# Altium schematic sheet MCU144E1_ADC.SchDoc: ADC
size 431 x 279 mm; DrawnBy: Gustavo Martinez; DocumentNumber: 9; SheetNumber: 3; SheetTotal: 8; PageSetup: Record=PageOptions¦CenterHorizontal=True¦CenterVertical=True¦PrintScale=1.00¦XCorrection=1.00¦YCorrection=1.00¦PrintKind=0¦BorderSize=5000000¦LeftOffset=0¦BottomOffset=0¦Orientation=2¦PaperLength=1000¦PaperWidth=1000¦Scale=100¦PaperSource=15¦PrintQuality=600¦MediaType=1¦DitherType=10¦PaperKind=Letter¦PrintScaleMode=1
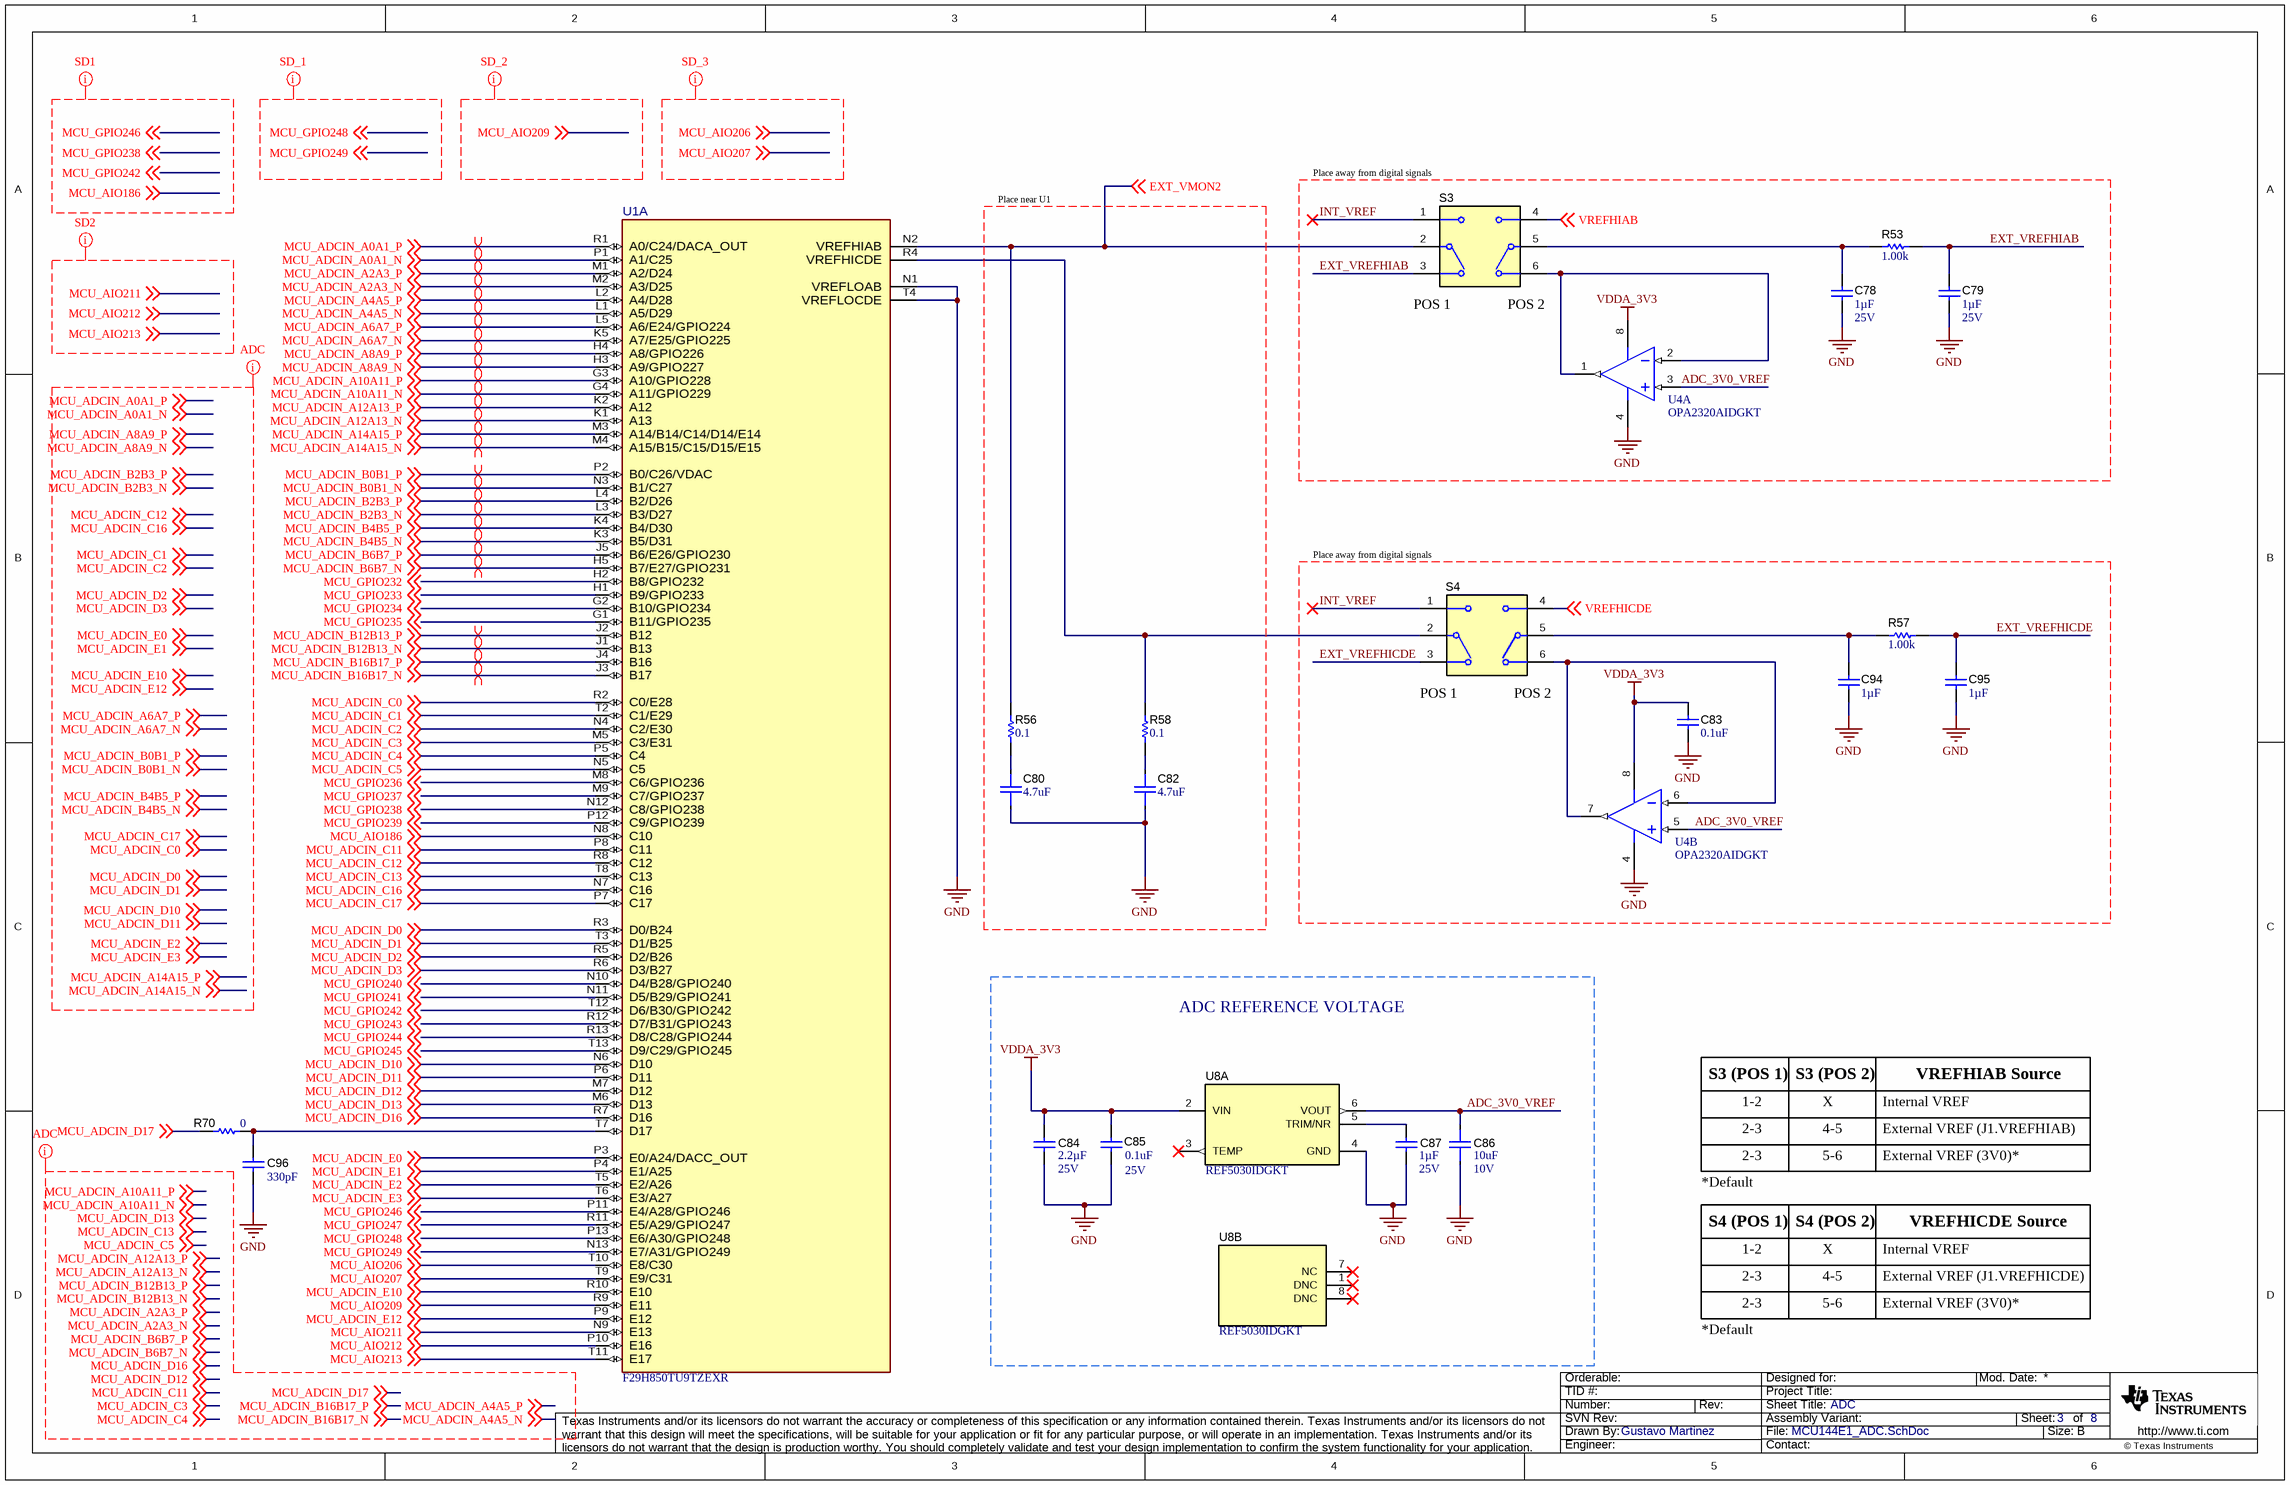
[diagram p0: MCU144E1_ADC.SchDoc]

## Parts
C78  ValueDisplayed: 1µF  VDC_V: 25V  [0402]  (hidden comment: GRM155R61E105KE11D)
C79  ValueDisplayed: 1µF  VDC_V: 25V  [0402]  (hidden comment: GRM155R61E105KE11D)
C80  ValueDisplayed: 4.7uF  [FP-GRM155C61E475ME15D_0402-MFG]  (hidden comment: GRM155C61E475ME15D)
C82  ValueDisplayed: 4.7uF  [FP-GRM155C61E475ME15D_0402-MFG]  (hidden comment: GRM155C61E475ME15D)
C83  ValueDisplayed: 0.1uF  [0402]  (hidden comment: GRM155R71E104KE14D)
C84  Value2: 25V  ValueDisplayed: 2.2µF  [0402]  (hidden comment: GRM155R61E225ME15D)
C85  VDC_V: 25V  ValueDisplayed: 0.1uF  [0402]  (hidden comment: GRM155R71E104KE14D)
C86  VDC_V: 10V  ValueDisplayed: 10uF  [FP-GRM155R61A106ME18D_0402-MFG]  (hidden comment: GRM155R61A106ME18D)
C87  ValueDisplayed: 1µF  VDC_V: 25V  [0402]  (hidden comment: GRM155R61E105KE11D)
C94  ValueDisplayed: 1µF  [0402]  (hidden comment: GRM155R61E105KE11D)
C95  ValueDisplayed: 1µF  [0402]  (hidden comment: GRM155R61E105KE11D)
C96  value 330pF  [0603]  (hidden comment: 885012006060)
R53  ValueDisplayed: 1.00k  [0402]  (hidden comment: ERJ-2RKF1001X)
R56  ValueDisplayed: 0.1  [0402]  (hidden comment: ERJ2BWFR100X)
R57  ValueDisplayed: 1.00k  [0402]  (hidden comment: ERJ-2RKF1001X)
R58  ValueDisplayed: 0.1  [0402]  (hidden comment: ERJ2BWFR100X)
R70  ValueDisplayed: 0  [0603]  (hidden comment: ERJ-3GEY0R00V)
S3  CAS-D20TA  [SW_CAS-D20TA]  (value not drawn)
S4  CAS-D20TA  [SW_CAS-D20TA]  (value not drawn)
U1  F29H850TU9TZEXR  [ZEX0256A-MFG]  (part A of 4)
U4  OPA2320AIDGKT  [DGK0008A_N]  (parts A,B of 2)
U8  REF5030IDGKT  [DGK0008A_N]  (parts A,B of 2)

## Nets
GND: C78.2 C79.2 C80.1 C82.1 C83.2 C84.2 C85.2 C86.1 C87.2 C94.2 C95.2 C96.2 U1.N1(VREFLOAB) U1.T4(VREFLOCDE) U4.4(V-) U8.4(GND)
VDDA_3V3: C83.1 C84.1 C85.1 U4.8(V+) U8.2(VIN)
ADC_3V0_VREF: C86.2 U4.3(IN_A+) U4.5(IN_B+) U8.6(VOUT)
EXT_VMON2: R56.2 S3.2(C) U1.N2(VREFHIAB) ; off-sheet EXT_VMON2
EXT_VREFHIAB: C79.1 R53.2 S3.3
EXT_VREFHICDE: C95.1 R57.2 S4.3
INT_VREF: S3.1 S4.1
MCU_ADCIN_A0A1_N: U1.P1(A1/C25) ; off-sheet MCU_ADCIN_A0A1_N
MCU_ADCIN_A0A1_P: U1.R1(A0/C24/DACA_OUT) ; off-sheet MCU_ADCIN_A0A1_P
MCU_ADCIN_A2A3_N: U1.M2(A3/D25) ; off-sheet MCU_ADCIN_A2A3_N
MCU_ADCIN_A2A3_P: U1.M1(A2/D24) ; off-sheet MCU_ADCIN_A2A3_P
MCU_ADCIN_A4A5_N: U1.L1(A5/D29) ; off-sheet MCU_ADCIN_A4A5_N
MCU_ADCIN_A4A5_P: U1.L2(A4/D28) ; off-sheet MCU_ADCIN_A4A5_P
MCU_ADCIN_A6A7_N: U1.K5(A7/E25/GPIO225) ; off-sheet MCU_ADCIN_A6A7_N
MCU_ADCIN_A6A7_P: U1.L5(A6/E24/GPIO224) ; off-sheet MCU_ADCIN_A6A7_P
MCU_ADCIN_A8A9_N: U1.H3(A9/GPIO227) ; off-sheet MCU_ADCIN_A8A9_N
MCU_ADCIN_A8A9_P: U1.H4(A8/GPIO226) ; off-sheet MCU_ADCIN_A8A9_P
MCU_ADCIN_A10A11_N: U1.G4(A11/GPIO229) ; off-sheet MCU_ADCIN_A10A11_N
MCU_ADCIN_A10A11_P: U1.G3(A10/GPIO228) ; off-sheet MCU_ADCIN_A10A11_P
MCU_ADCIN_A12A13_N: U1.K1(A13) ; off-sheet MCU_ADCIN_A12A13_N
MCU_ADCIN_A12A13_P: U1.K2(A12) ; off-sheet MCU_ADCIN_A12A13_P
MCU_ADCIN_A14A15_N: U1.M4(A15/B15/C15/D15/E15) ; off-sheet MCU_ADCIN_A14A15_N
MCU_ADCIN_A14A15_P: U1.M3(A14/B14/C14/D14/E14) ; off-sheet MCU_ADCIN_A14A15_P
MCU_ADCIN_B0B1_N: U1.N3(B1/C27) ; off-sheet MCU_ADCIN_B0B1_N
MCU_ADCIN_B0B1_P: U1.P2(B0/C26/VDAC) ; off-sheet MCU_ADCIN_B0B1_P
MCU_ADCIN_B2B3_N: U1.L3(B3/D27) ; off-sheet MCU_ADCIN_B2B3_N
MCU_ADCIN_B2B3_P: U1.L4(B2/D26) ; off-sheet MCU_ADCIN_B2B3_P
MCU_ADCIN_B4B5_N: U1.K3(B5/D31) ; off-sheet MCU_ADCIN_B4B5_N
MCU_ADCIN_B4B5_P: U1.K4(B4/D30) ; off-sheet MCU_ADCIN_B4B5_P
MCU_ADCIN_B6B7_N: U1.H5(B7/E27/GPIO231) ; off-sheet MCU_ADCIN_B6B7_N
MCU_ADCIN_B6B7_P: U1.J5(B6/E26/GPIO230) ; off-sheet MCU_ADCIN_B6B7_P
MCU_ADCIN_B12B13_N: U1.J1(B13) ; off-sheet MCU_ADCIN_B12B13_N
MCU_ADCIN_B12B13_P: U1.J2(B12) ; off-sheet MCU_ADCIN_B12B13_P
MCU_ADCIN_B16B17_N: U1.J3(B17) ; off-sheet MCU_ADCIN_B16B17_N
MCU_ADCIN_B16B17_P: U1.J4(B16) ; off-sheet MCU_ADCIN_B16B17_P
MCU_ADCIN_C0: U1.R2(C0/E28) ; off-sheet MCU_ADCIN_C0
MCU_ADCIN_C1: U1.T2(C1/E29) ; off-sheet MCU_ADCIN_C1
MCU_ADCIN_C2: U1.N4(C2/E30) ; off-sheet MCU_ADCIN_C2
MCU_ADCIN_C3: U1.M5(C3/E31) ; off-sheet MCU_ADCIN_C3
MCU_ADCIN_C4: U1.P5(C4) ; off-sheet MCU_ADCIN_C4
MCU_ADCIN_C5: U1.N5(C5) ; off-sheet MCU_ADCIN_C5
MCU_ADCIN_C11: U1.P8(C11) ; off-sheet MCU_ADCIN_C11
MCU_ADCIN_C12: U1.R8(C12) ; off-sheet MCU_ADCIN_C12
MCU_ADCIN_C13: U1.T8(C13) ; off-sheet MCU_ADCIN_C13
MCU_ADCIN_C16: U1.N7(C16) ; off-sheet MCU_ADCIN_C16
MCU_ADCIN_C17: U1.P7(C17) ; off-sheet MCU_ADCIN_C17
MCU_ADCIN_D0: U1.R3(D0/B24) ; off-sheet MCU_ADCIN_D0
MCU_ADCIN_D1: U1.T3(D1/B25) ; off-sheet MCU_ADCIN_D1
MCU_ADCIN_D2: U1.R5(D2/B26) ; off-sheet MCU_ADCIN_D2
MCU_ADCIN_D3: U1.R6(D3/B27) ; off-sheet MCU_ADCIN_D3
MCU_ADCIN_D10: U1.N6(D10) ; off-sheet MCU_ADCIN_D10
MCU_ADCIN_D11: U1.P6(D11) ; off-sheet MCU_ADCIN_D11
MCU_ADCIN_D12: U1.M7(D12) ; off-sheet MCU_ADCIN_D12
MCU_ADCIN_D13: U1.M6(D13) ; off-sheet MCU_ADCIN_D13
MCU_ADCIN_D16: U1.R7(D16) ; off-sheet MCU_ADCIN_D16
MCU_ADCIN_D17: R70.1 ; off-sheet MCU_ADCIN_D17
MCU_ADCIN_E0: U1.P3(E0/A24/DACC_OUT) ; off-sheet MCU_ADCIN_E0
MCU_ADCIN_E1: U1.P4(E1/A25) ; off-sheet MCU_ADCIN_E1
MCU_ADCIN_E2: U1.T5(E2/A26) ; off-sheet MCU_ADCIN_E2
MCU_ADCIN_E3: U1.T6(E3/A27) ; off-sheet MCU_ADCIN_E3
MCU_ADCIN_E10: U1.R10(E10) ; off-sheet MCU_ADCIN_E10
MCU_ADCIN_E12: U1.P9(E12) ; off-sheet MCU_ADCIN_E12
MCU_AIO186: U1.N8(C10) ; off-sheet MCU_AIO186
MCU_AIO206: U1.T10(E8/C30) ; off-sheet MCU_AIO206
MCU_AIO207: U1.T9(E9/C31) ; off-sheet MCU_AIO207
MCU_AIO209: U1.R9(E11) ; off-sheet MCU_AIO209
MCU_AIO211: U1.N9(E13) ; off-sheet MCU_AIO211
MCU_AIO212: U1.P10(E16) ; off-sheet MCU_AIO212
MCU_AIO213: U1.T11(E17) ; off-sheet MCU_AIO213
MCU_GPIO232: U1.H2(B8/GPIO232) ; off-sheet MCU_GPIO232
MCU_GPIO233: U1.H1(B9/GPIO233) ; off-sheet MCU_GPIO233
MCU_GPIO234: U1.G2(B10/GPIO234) ; off-sheet MCU_GPIO234
MCU_GPIO235: U1.G1(B11/GPIO235) ; off-sheet MCU_GPIO235
MCU_GPIO236: U1.M8(C6/GPIO236) ; off-sheet MCU_GPIO236
MCU_GPIO237: U1.M9(C7/GPIO237) ; off-sheet MCU_GPIO237
MCU_GPIO238: U1.N12(C8/GPIO238) ; off-sheet MCU_GPIO238
MCU_GPIO239: U1.P12(C9/GPIO239) ; off-sheet MCU_GPIO239
MCU_GPIO240: U1.N10(D4/B28/GPIO240) ; off-sheet MCU_GPIO240
MCU_GPIO241: U1.N11(D5/B29/GPIO241) ; off-sheet MCU_GPIO241
MCU_GPIO242: U1.T12(D6/B30/GPIO242) ; off-sheet MCU_GPIO242
MCU_GPIO243: U1.R12(D7/B31/GPIO243) ; off-sheet MCU_GPIO243
MCU_GPIO244: U1.R13(D8/C28/GPIO244) ; off-sheet MCU_GPIO244
MCU_GPIO245: U1.T13(D9/C29/GPIO245) ; off-sheet MCU_GPIO245
MCU_GPIO246: U1.P11(E4/A28/GPIO246) ; off-sheet MCU_GPIO246
MCU_GPIO247: U1.R11(E5/A29/GPIO247) ; off-sheet MCU_GPIO247
MCU_GPIO248: U1.P13(E6/A30/GPIO248) ; off-sheet MCU_GPIO248
MCU_GPIO249: U1.N13(E7/A31/GPIO249) ; off-sheet MCU_GPIO249
VREFHIAB: S3.4 ; off-sheet VREFHIAB
VREFHICDE: S4.4 ; off-sheet VREFHICDE
NetC78_1: C78.1 R53.1 S3.5(C)
NetC80_2: C80.2 R56.1
NetC82_2: C82.2 R58.1
NetC87_1: C87.1 U8.5(TRIM/NR)
NetC94_1: C94.1 R57.1 S4.5(C)
NetC96_1: C96.1 R70.2 U1.T7(D17)
NetR58_2: R58.2 S4.2(C) U1.R4(VREFHICDE)
NetS3_6: S3.6 U4.1(OUT_A) U4.2(IN_A-)
NetS4_6: S4.6 U4.6(IN_B-) U4.7(OUT_B)

Not connected (* = marked no-connect by the designer): U8 1(DNC)* 3(TEMP)* 7(NC)* 8(DNC)*

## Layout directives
differential pair; differential pair class 100OHM; differential pair class 100OHM: MCU_ADCIN_A0A1_P
differential pair; differential pair class 100OHM: MCU_ADCIN_A0A1_N, MCU_ADCIN_A2A3_N, MCU_ADCIN_A2A3_P, MCU_ADCIN_A4A5_N, MCU_ADCIN_A4A5_P, MCU_ADCIN_A6A7_N, MCU_ADCIN_A6A7_P, MCU_ADCIN_A8A9_N, MCU_ADCIN_A8A9_P, MCU_ADCIN_A10A11_N, MCU_ADCIN_A10A11_P, MCU_ADCIN_A12A13_N, MCU_ADCIN_A12A13_P, MCU_ADCIN_A14A15_N, MCU_ADCIN_A14A15_P, MCU_ADCIN_B0B1_N, MCU_ADCIN_B0B1_P, MCU_ADCIN_B2B3_N, MCU_ADCIN_B2B3_P, MCU_ADCIN_B4B5_N, MCU_ADCIN_B4B5_P, MCU_ADCIN_B6B7_N, MCU_ADCIN_B6B7_P, MCU_ADCIN_B12B13_N, MCU_ADCIN_B12B13_P, MCU_ADCIN_B16B17_N, MCU_ADCIN_B16B17_P
net class SD1: MCU_AIO186, MCU_GPIO238, MCU_GPIO242, MCU_GPIO246
net class SD2: MCU_AIO211, MCU_AIO212, MCU_AIO213
net class SD_1: MCU_GPIO248, MCU_GPIO249
net class SD_2: MCU_AIO209
net class SD_3: MCU_AIO206, MCU_AIO207
net class ADC: GND, MCU_ADCIN_A0A1_N, MCU_ADCIN_A0A1_P, MCU_ADCIN_A2A3_N, MCU_ADCIN_A2A3_P, MCU_ADCIN_A4A5_N, MCU_ADCIN_A4A5_P, MCU_ADCIN_A6A7_N, MCU_ADCIN_A6A7_P, MCU_ADCIN_A8A9_N, MCU_ADCIN_A8A9_P, MCU_ADCIN_A10A11_N, MCU_ADCIN_A10A11_P, MCU_ADCIN_A12A13_N, MCU_ADCIN_A12A13_P, MCU_ADCIN_A14A15_N, MCU_ADCIN_A14A15_P, MCU_ADCIN_B0B1_N, MCU_ADCIN_B0B1_P, MCU_ADCIN_B2B3_N, MCU_ADCIN_B2B3_P, MCU_ADCIN_B4B5_N, MCU_ADCIN_B4B5_P, MCU_ADCIN_B6B7_N, MCU_ADCIN_B6B7_P, MCU_ADCIN_B12B13_N, MCU_ADCIN_B12B13_P, MCU_ADCIN_B16B17_N, MCU_ADCIN_B16B17_P, MCU_ADCIN_C0, MCU_ADCIN_C1, MCU_ADCIN_C2, MCU_ADCIN_C3, MCU_ADCIN_C4, MCU_ADCIN_C5, MCU_ADCIN_C11, MCU_ADCIN_C12, MCU_ADCIN_C13, MCU_ADCIN_C16, MCU_ADCIN_C17, MCU_ADCIN_D0, MCU_ADCIN_D1, MCU_ADCIN_D2, MCU_ADCIN_D3, MCU_ADCIN_D10, MCU_ADCIN_D11, MCU_ADCIN_D12, MCU_ADCIN_D13, MCU_ADCIN_D16, MCU_ADCIN_D17, MCU_ADCIN_E0, MCU_ADCIN_E1, MCU_ADCIN_E2, MCU_ADCIN_E3, MCU_ADCIN_E10, MCU_ADCIN_E12, MCU_AIO206, MCU_AIO207, MCU_AIO209, MCU_AIO211, MCU_AIO212, MCU_AIO213, MCU_GPIO246, MCU_GPIO247, MCU_GPIO248, MCU_GPIO249

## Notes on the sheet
- Place near U1
- (near S3) Place away from digital signals
- (near S3) POS 1
- (near S3) POS 2
- (near S4) Place away from digital signals
- (near S4) POS 1
- (near S4) POS 2
- ADC REFERENCE VOLTAGE
- S3 (POS 1)
- 1-2
- S3 (POS 2)
- X
- Internal VREF
- VREFHIAB Source
- 2-3
- 4-5
- 5-6
- External VREF (3V0)*
- External VREF (J1.VREFHIAB)
- *Default
- S4 (POS 1)
- S4 (POS 2)
- VREFHICDE Source
- External VREF (J1.VREFHICDE)

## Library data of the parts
C78 C79 C87 = CMP-0086061-1: CAP, CERM, 1 µF, 25 V,+/- 10%, X5R, 0402; Manufacturer: MuRata; SizeX_mm: 1; AEC Category: Q200; SizeAreaWB_mm2: 3; U/M: EA; TaMin_C: -55°C; AEC Qualified: N; SizeZ_mm: 0.6; TaMax_C: 85°C; SizeArea_mm2: 0.5; Value: 1uF
C80 C82 = CMP-0120206-1: 4.7 µF ±20% 25V Ceramic Capacitor X5S 0402 (1005 Metric); Manufacturer: Murata; AEC Qualified: No; Cap_F: 4.7µF; SizeZ_mm: 0.7mm; TempCo: 22%; Value: 4.7µF
C83 = CMP-0006659-2: CAP, CERM, 0.1 uF, 25 V, +/- 10%, X7R, 0402; Manufacturer: MuRata; TaMin_C: -55°C; Polarized: N; SizeAreaWB_mm2: 3; Value1: Unknown; U/M: EA; Value: 0.1uF; TaMax_C: 125°C; SizeZ_mm: 0.6; SizeX_mm: 1; SizeY_mm: 0.5; Value2: 25V; Cap_F: 100nF; AEC Category: Q200
C84 = CMP-0081010-1: CAP, CERM, 2.2 µF, 25 V,+/- 20%, X5R, 0402; Manufacturer: MuRata; TaMin_C: -55°C; Polarized: N; SizeAreaWB_mm2: 3; U/M: EA; Value: 2.2uF; TaMax_C: 85°C; SizeZ_mm: 0.6; SizeX_mm: 1; SizeY_mm: 0.5; AEC Category: Q200
C85 = CMP-0006659-2: CAP, CERM, 0.1 uF, 25 V, +/- 10%, X7R, 0402; Manufacturer: MuRata; TaMin_C: -55°C; Polarized: N; SizeAreaWB_mm2: 3; Value1: Unknown; U/M: EA; Value: 0.1uF; TaMax_C: 125°C; SizeZ_mm: 0.6; SizeX_mm: 1; SizeY_mm: 0.5; Cap_F: 100nF; AEC Category: Q200
C86 = CMP-0120207-1: 10 µF ±20% 10V Ceramic Capacitor X5R 0402 (1005 Metric); Manufacturer: Murata; TempCo: 15%; Value: 10µF; SizeZ_mm: 0.7mm; AEC Qualified: No
C94 C95 = CMP-0086061-1: CAP, CERM, 1 µF, 25 V,+/- 10%, X5R, 0402; Manufacturer: MuRata; SizeX_mm: 1; AEC Category: Q200; SizeAreaWB_mm2: 3; U/M: EA; Value2: 25V; TaMin_C: -55°C; AEC Qualified: N; SizeZ_mm: 0.6; TaMax_C: 85°C; SizeArea_mm2: 0.5; Value: 1uF
C96 = CMP-0006823-4: CAP, CERM, 330 pF, 50 V, +/- 5%, C0G/NP0, 0603; Manufacturer: Wurth Elektronik; TaMin_C: -55°C; Polarized: N; SizeAreaWB_mm2: 4.68; Value1: Unknown; U/M: EA; TaMax_C: 125°C; SizeZ_mm: 1; SizeX_mm: 1.6; SizeY_mm: 0.8; Value2: 50V; SizeArea_mm2: 1.28; AEC Category: Q200
R53 R57 = CMP-0026657-1: RES, 1.00 k, 1%, 0.1 W, 0402; Manufacturer: Panasonic; Power_W: 100mW; TempCo: 100 ppm/C; Value_Code: 1k00; U/M: EA; Value: 1.00k; EIA_Code: E96; Res_ohm: 1k; SizeX_mm: 1; SizeY_mm: 0.5; SizeZ_mm: 0.6; Value2: 0.1W; VDC_V: 50V; AEC Category: Q200
R56 R58 = CMP-0078660-1: RES, 0.1, 1%, 0.25 W, 0402; Manufacturer: Panasonic; Power_W: 250mW; TempCo: 300 ppm/C; Value_Code: R100; Value: 0.1; EIA_Code: E96; Res_ohm: 1d; SizeX_mm: 1; SizeY_mm: 0.5; SizeZ_mm: 0.6; Value2: 0.25W; AEC Qualified: N; AEC Category: Q200
R70 = CMP-0025874-4: RES, 0, 5%, 0.1 W, AEC-Q200 Grade 0, 0603; Manufacturer: Panasonic; Power_W: 100mW; TempCo: 600 ppm/C; Value_Code: 0000; Value: 0; EIA_Code: E24; SizeX_mm: 1.6; SizeY_mm: 0.8; SizeZ_mm: 1; Value2: 0.1W; SizeArea_mm2: 1.28; AEC Qualified: Y; VDC_V: 50V; AEC Category: Q200; SizeAreaWB_mm2: 4.68
S3 S4 = CMP-0002233-1: Switch, Dual SPDT,  2 Pos, 0.1A, 6VDC, SMD; Manufacturer: Copal Electronics; CurrentRating_mA: 100A; SwitchFunction: On-On; VDC_V: 6V; PositionCount: 2
U1 = CMP-0121934-2: Real-Time Microcontroller; Manufacturer: Texas Instruments; SizeZ_mm: 1.3mm; AEC Qualified: No; Core Architecture: C29x; Data Bus Width: 64bits; Frequency_Fixed: 200MHz; Interface: I2C,SPI,UART,CAN,LIN,IrDA,Other; Max Supply Voltage: 3.63V; Memory Size: 4MBytes; Memory Type: FLASH; Min Supply Voltage: 1.14V; Number Of A/D Converters: 5; Number Of Cores: 3; Number Of Ethernet Channels: 1; Number Of I2C Channels: 2; Number Of Pwm Channels: 36; Number Of Timers/Counters: 12; Number Of Uart Channels: 6; Ram Size: 452KBytes; Standoff Height: 0.25mm; TaMax_C: +105°C; TaMin_C: -40°C; TJmax_C: +125°C; AEC Category: Q200; CompType: IC
U4 = CMP-0040680-2: Precision, Zero-Crossover, 20MHz, 0.9pA Ib, RRIO, CMOS Operational Amplifier, DGK0008A (VSSOP-8); Manufacturer: Texas Instruments; Vio (25C)(Max)(mV): 0.15; Sub Family: High Output Current Amplifier (>=50mA), Low Input Bias Current Amp (<=10pA), Low Noise Amp (<=10nV/rtHz), Low Offset Voltage Amplifier (<=500uV), Low Supply Voltage Amplifier (<=2.7V), Precision Amplifier; Iq per channel(Max)(mA): 1.6; Eco-Plan: Green (RoHS & no Sb/Br); IIB(Max)(pA): 400; Total Supply Voltage(Max)(+5V is 5, +/-5V is 10): 5.5; Slew Rate(Typ)(V/us): 10; CMRR(Min)(dB): 100; Vn at 1kHz(Typ)(nV/rtHz): 8.5; Number of Channels: 2; Offset Drift(Typ)(uV/C): 1.5; Total Supply Voltage(Min)(+5V is 5, +/-5V is 10): 1.8; AEC Category: Q200; AEC Qualified: N; CompType: IC; SizeAreaWB_mm2: 23.6; SizeArea_mm2: 14.7; SizeX_mm: 4.9; SizeY_mm: 3; SizeZ_mm: 1.1
U8 = CMP-0032596-2: Low Noise, Very Low Drift, Precision Series Voltage Reference, DGK0008A (VSSOP-8); Manufacturer: Texas Instruments; Temp Coeff(Max)(ppm/ degree C): 3; Iout/Iz(Max)(mA): 10; VI(Min)(V): 3.2; Eco-Plan: Green (RoHS & no Sb/Br); Initial Accuracy @ 25/deg C(%): 0.05; Iq(Max)(uA): 1000; VI(Max)(V): 18; Rating: Catalog; AEC Category: Q200; AEC Qualified: N; CompType: IC; SizeAreaWB_mm2: 23.6; SizeArea_mm2: 14.7; SizeX_mm: 4.9; SizeZ_mm: 1.1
